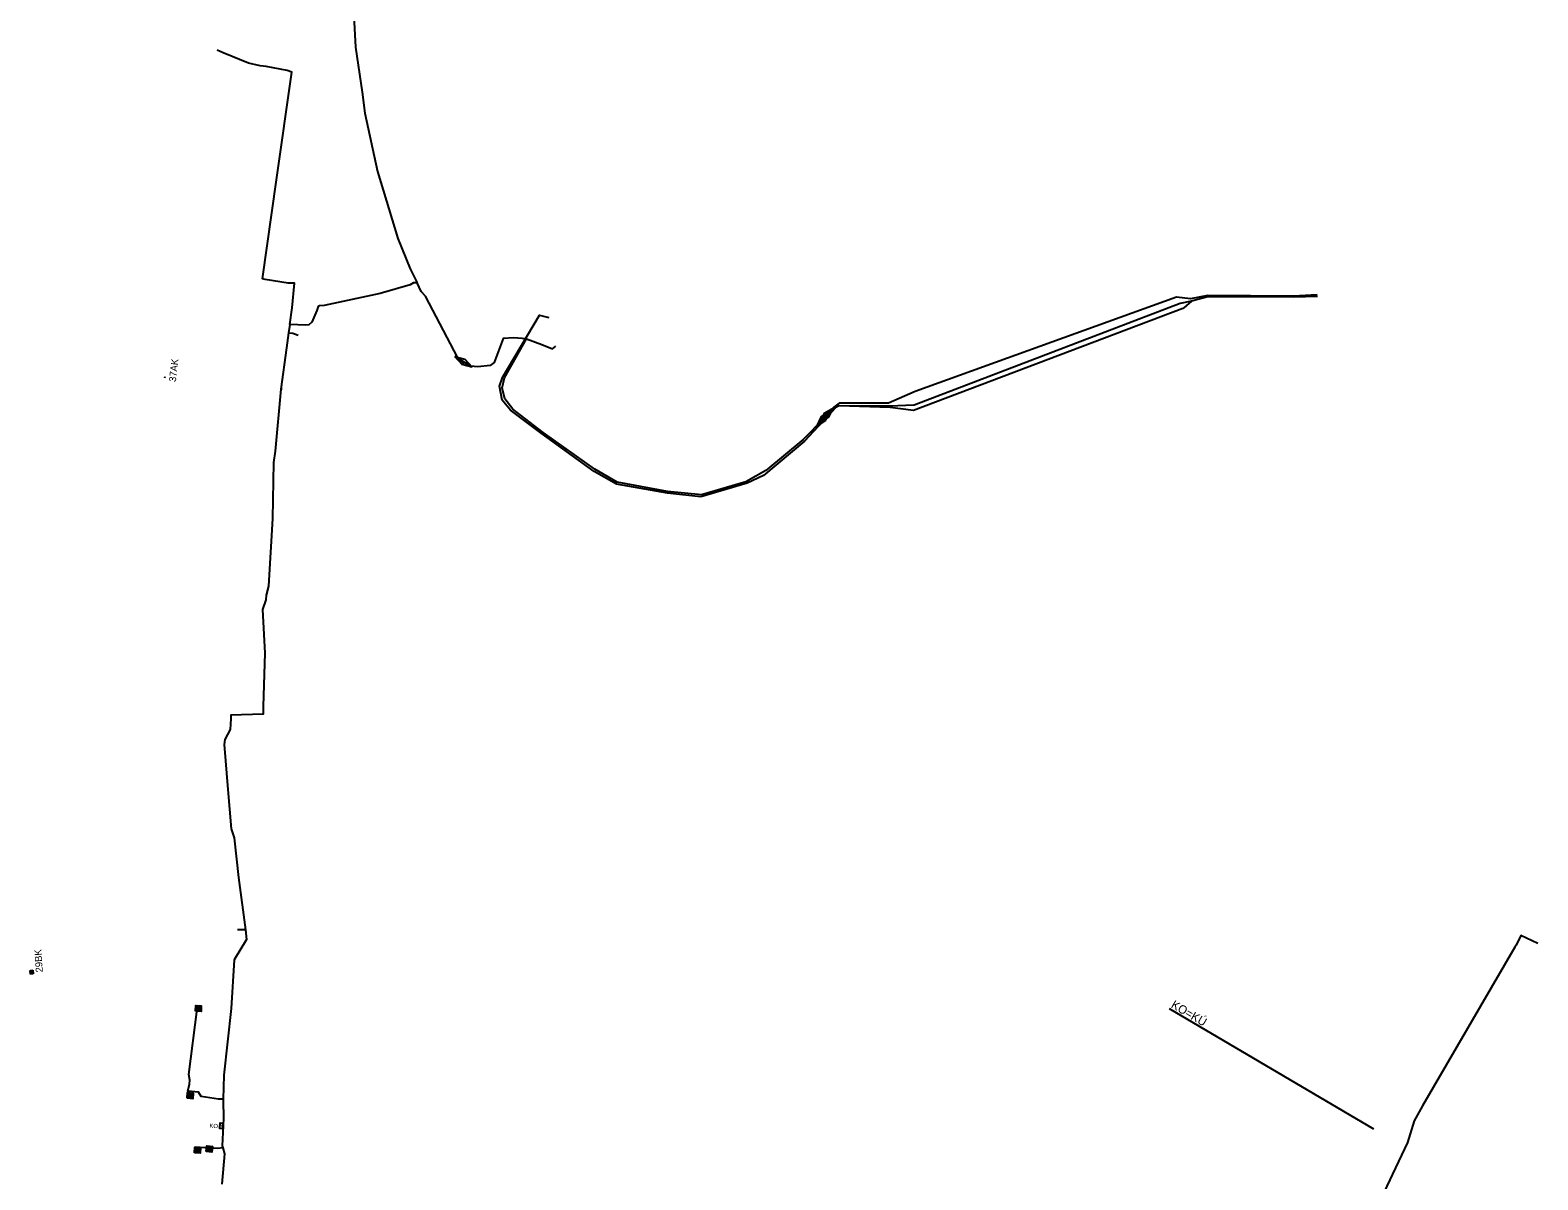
# Model space of a CAD drawing. Extents: x -598638 to -597933, y -1164002 to -1161904.
# Drawn here: x -598468 to -597933, y -1162612 to -1162205 of the extents above; entities that cross this region are included whole.
import ezdxf

# ---------------------------------------------------------------- set-up
doc = ezdxf.new("R2010")
doc.units = 0
for name, color, linetype in [('Vrstva 1', 7, 'Continuous'), ('Vrstva 11', 7, 'Continuous'), ('Vrstva 12', 7, 'Continuous'), ('Vrstva 25', 7, 'Continuous'), ('Vrstva 26', 7, 'Continuous'), ('Vrstva 28', 7, 'Continuous'), ('Vrstva 3', 7, 'Continuous'), ('Vrstva 31', 7, 'Continuous'), ('Vrstva 36', 7, 'Continuous')]:
    doc.layers.add(name, color=color, linetype=linetype)

msp = doc.modelspace()

# ---------------------------------------------------------------- linework, layer by layer
at = {"layer": 'Vrstva 1'}
msp.add_line((-598064.09, -1162551.17), (-597991.64, -1162593.75), dxfattribs=at)
at = {"layer": 'Vrstva 12'}
for p, q in [((-598467.77, -1162537.62), (-598466.85, -1162537.57)), ((-598467.68, -1162538.96), (-598467.77, -1162537.62)), ((-598466.73, -1162538.87), (-598467.68, -1162538.96)), ((-598466.85, -1162537.57), (-598466.73, -1162538.87))]:
    msp.add_line(p, q, dxfattribs=at)
at = {"layer": 'Vrstva 25'}
msp.add_lwpolyline([(-598399.55, -1162593.72), (-598400.55, -1162593.67), (-598400.45, -1162591.67), (-598399.45, -1162591.72), (-598399.55, -1162593.72)], dxfattribs=at)
at = {"layer": 'Vrstva 26'}
for points in [[(-598011.45, -1162298.92), (-598019.97, -1162299.17), (-598050.29, -1162298.98), (-598056.17, -1162300.49), (-598058.88, -1162302.93)], [(-598060.11, -1162301.37), (-598154.38, -1162337.34), (-598163.12, -1162337.7), (-598181.03, -1162337.65), (-598182.25, -1162338.25), (-598193.26, -1162350.18), (-598207.85, -1162362.29), (-598213.6, -1162365.05), (-598230, -1162369.89), (-598241.82, -1162368.56), (-598259.92, -1162365.37), (-598267.91, -1162360.87), (-598286.7, -1162347.32), (-598297.52, -1162339.13), (-598300.49, -1162335.57), (-598301.41, -1162330.6), (-598300.36, -1162327.61), (-598287.22, -1162305.48), (-598283.93, -1162306.33)], [(-598058.88, -1162302.93), (-598059.2, -1162303.1), (-598154.64, -1162339.27), (-598162.93, -1162338.26), (-598181.03, -1162337.65)], [(-598056.17, -1162300.49), (-598060.11, -1162301.37)]]:
    msp.add_lwpolyline(points, dxfattribs=at)
at = {"layer": 'Vrstva 28'}
msp.add_line((-598376.94, -1162317.06), (-598378.88, -1162331.68), dxfattribs=at)
for points in [[(-598353.9, -1162184.09), (-598352.41, -1162210.55), (-598350.05, -1162226.44), (-598349.11, -1162233.96), (-598344.67, -1162254.61), (-598337.45, -1162278.29), (-598333.08, -1162289.1), (-598330.61, -1162294.08)], [(-598375.78, -1162308.82), (-598374.85, -1162302.85), (-598374.07, -1162294.15), (-598376.34, -1162294.11), (-598384.44, -1162292.82), (-598385.42, -1162292.58), (-598380.46, -1162257.51), (-598375.06, -1162219.37), (-598376.64, -1162218.79), (-598384.12, -1162217.4), (-598386.19, -1162217.16), (-598390.41, -1162216.19), (-598399.4, -1162212.6), (-598401.45, -1162211.61)], [(-598330.61, -1162294.08), (-598331.9, -1162294.01), (-598333.02, -1162294.74), (-598343.76, -1162297.84), (-598363.52, -1162302.05), (-598365.21, -1162302.15), (-598365.71, -1162302.43), (-598366.21, -1162303.85), (-598367.94, -1162308.01), (-598369.04, -1162308.96), (-598370.03, -1162309.04), (-598375.78, -1162308.82), (-598376.18, -1162311.7), (-598376.94, -1162317.06)], [(-598376.18, -1162311.7), (-598374.7, -1162311.85), (-598372.76, -1162312.62)], [(-598378.5, -1162331.73), (-598378.88, -1162331.68), (-598380.93, -1162353.73), (-598381.48, -1162357.65), (-598381.89, -1162377.53), (-598383.31, -1162401.46), (-598384.09, -1162404.69), (-598384.23, -1162406.31), (-598385.47, -1162409.72), (-598384.6, -1162425.24), (-598385.17, -1162443.97), (-598385.21, -1162446.81), (-598396.64, -1162447.23), (-598396.63, -1162448.48), (-598396.85, -1162452.27), (-598398.8, -1162455.76), (-598398.99, -1162457.62), (-598397.75, -1162473.54), (-598396.55, -1162487.5), (-598395.42, -1162490.7), (-598393.97, -1162504.76), (-598391.49, -1162523.29), (-598391.04, -1162526.62), (-598395.41, -1162533.9), (-598396.52, -1162551.17), (-598399.1, -1162574.72), (-598399.38, -1162583.21), (-598399.4, -1162583.79), (-598399.26, -1162589.82), (-598399.4, -1162592.7), (-598399.72, -1162599.74), (-598399.5, -1162600.49), (-598398.9, -1162602.55), (-598399.81, -1162613.38)], [(-598391.49, -1162523.29), (-598394.32, -1162523.26)], [(-597933.37, -1162528.05), (-597939.36, -1162525.29), (-597941.1, -1162528.7), (-597941.55, -1162529.41), (-597974.27, -1162585.61), (-597977.15, -1162590.9), (-597979.51, -1162598.61), (-597991.15, -1162623.06), (-598003.68, -1162641.63), (-598026.57, -1162675.67), (-598042.6, -1162699.78), (-598060.46, -1162726.16), (-598080.92, -1162759.23), (-598091.38, -1162776.88), (-598100.13, -1162791.04)], [(-598399.38, -1162583.21), (-598401.01, -1162583.26), (-598407.18, -1162582.31), (-598408.06, -1162580.8), (-598411.86, -1162580.41), (-598411.34, -1162577.93), (-598411.15, -1162576.51), (-598411.49, -1162574.44), (-598408.61, -1162551.32), (-598409.15, -1162551.04)], [(-598411.86, -1162580.41), (-598412.03, -1162581.9)], [(-598399.4, -1162592.7), (-598400, -1162592.7)], [(-598399.5, -1162600.49), (-598401.2, -1162600.74), (-598404.88, -1162600.51), (-598405.9, -1162600.5), (-598409.05, -1162600.18), (-598409.47, -1162601.28)], [(-598404.88, -1162600.51), (-598405.24, -1162600.75)]]:
    msp.add_lwpolyline(points, dxfattribs=at)
at = {"layer": 'Vrstva 3'}
for p, q in [((-598407.74, -1162552.12), (-598409.12, -1162550.57)), ((-598407.21, -1162552.15), (-598409.09, -1162550.04)), ((-598407.18, -1162551.62), (-598408.56, -1162550.07)), ((-598407.15, -1162551.1), (-598408.04, -1162550.1)), ((-598407.12, -1162550.57), (-598407.51, -1162550.13)), ((-598408.8, -1162552.06), (-598409.19, -1162551.63)), ((-598408.27, -1162552.09), (-598409.16, -1162551.1)), ((-598411.71, -1162582.93), (-598412.08, -1162582.49)), ((-598411.18, -1162582.97), (-598412.04, -1162581.96)), ((-598410.65, -1162583.02), (-598412, -1162581.43)), ((-598410.12, -1162583.06), (-598411.95, -1162580.91)), ((-598410.08, -1162582.53), (-598411.43, -1162580.95)), ((-598410.03, -1162582), (-598410.9, -1162580.99)), ((-598409.99, -1162581.47), (-598410.37, -1162581.03)), ((-598409.14, -1162602.31), (-598409.51, -1162601.87)), ((-598408.61, -1162602.35), (-598409.48, -1162601.34)), ((-598408.08, -1162602.38), (-598409.44, -1162600.82)), ((-598407.55, -1162602.42), (-598409.4, -1162600.29)), ((-598407.51, -1162601.89), (-598408.87, -1162600.32)), ((-598407.47, -1162601.36), (-598408.35, -1162600.36)), ((-598407.44, -1162600.84), (-598407.82, -1162600.4)), ((-598404.93, -1162601.79), (-598405.3, -1162601.34)), ((-598404.4, -1162601.84), (-598405.24, -1162600.81)), ((-598403.87, -1162601.89), (-598405.19, -1162600.28)), ((-598403.35, -1162601.95), (-598405.14, -1162599.75)), ((-598403.29, -1162601.42), (-598404.61, -1162599.81)), ((-598403.24, -1162600.89), (-598404.08, -1162599.86)), ((-598403.19, -1162600.36), (-598403.55, -1162599.91))]:
    msp.add_line(p, q, dxfattribs=at)
for points in [[(-598409.21, -1162552.04), (-598409.09, -1162550.04), (-598407.1, -1162550.16), (-598407.21, -1162552.15)], [(-598409.21, -1162552.04), (-598409.09, -1162550.04), (-598407.1, -1162550.16), (-598407.21, -1162552.15)], [(-598412.11, -1162582.9), (-598411.95, -1162580.91), (-598409.96, -1162581.06), (-598410.12, -1162583.06)], [(-598412.11, -1162582.9), (-598411.95, -1162580.91), (-598409.96, -1162581.06), (-598410.12, -1162583.06)], [(-598409.54, -1162602.28), (-598409.4, -1162600.29), (-598407.41, -1162600.43), (-598407.55, -1162602.42)], [(-598409.54, -1162602.28), (-598409.4, -1162600.29), (-598407.41, -1162600.43), (-598407.55, -1162602.42)], [(-598405.34, -1162601.74), (-598405.14, -1162599.75), (-598403.15, -1162599.96), (-598403.35, -1162601.95)], [(-598405.34, -1162601.74), (-598405.14, -1162599.75), (-598403.15, -1162599.96), (-598403.35, -1162601.95)]]:
    msp.add_lwpolyline(points, close=True, dxfattribs=at)
for points in [[(-598409.21, -1162552.04), (-598409.09, -1162550.04), (-598407.1, -1162550.16), (-598407.21, -1162552.15), (-598409.21, -1162552.04)], [(-598409.21, -1162552.04), (-598409.09, -1162550.04), (-598407.1, -1162550.16), (-598407.21, -1162552.15), (-598409.21, -1162552.04)], [(-598412.11, -1162582.9), (-598411.95, -1162580.91), (-598409.96, -1162581.06), (-598410.12, -1162583.06), (-598412.11, -1162582.9)], [(-598412.11, -1162582.9), (-598411.95, -1162580.91), (-598409.96, -1162581.06), (-598410.12, -1162583.06), (-598412.11, -1162582.9)], [(-598409.54, -1162602.28), (-598409.4, -1162600.29), (-598407.41, -1162600.43), (-598407.55, -1162602.42), (-598409.54, -1162602.28)], [(-598409.54, -1162602.28), (-598409.4, -1162600.29), (-598407.41, -1162600.43), (-598407.55, -1162602.42), (-598409.54, -1162602.28)], [(-598405.34, -1162601.74), (-598405.14, -1162599.75), (-598403.15, -1162599.96), (-598403.35, -1162601.95), (-598405.34, -1162601.74)], [(-598405.34, -1162601.74), (-598405.14, -1162599.75), (-598403.15, -1162599.96), (-598403.35, -1162601.95), (-598405.34, -1162601.74)]]:
    msp.add_lwpolyline(points, dxfattribs=at)
at = {"layer": 'Vrstva 31'}
for p, q in [((-598374.69, -1162302.88), (-598374.85, -1162302.85)), ((-598376.94, -1162317.06), (-598378.88, -1162331.68)), ((-598317.08, -1162320.35), (-598316.95, -1162320.35)), ((-598316.53, -1162320.99), (-598316.08, -1162320.88)), ((-598315.63, -1162321.96), (-598314.69, -1162321.73)), ((-598315.03, -1162322.58), (-598313.78, -1162322.28)), ((-598313.14, -1162323.31), (-598312.39, -1162323.13)), ((-598311.67, -1162323.7), (-598311.52, -1162323.66)), ((-598378.5, -1162331.73), (-598378.88, -1162331.68)), ((-598186.84, -1162342.83), (-598186.86, -1162342.37)), ((-598186.72, -1162343.41), (-598186.79, -1162342.43)), ((-598186.01, -1162342.92), (-598186.1, -1162341.64)), ((-598185.71, -1162342.16), (-598185.73, -1162341.18)), ((-598184.98, -1162341.17), (-598185.04, -1162340.4)), ((-598184.97, -1162341.7), (-598185.01, -1162340.42)), ((-598184.36, -1162339.78), (-598184.37, -1162339.63)), ((-598183.86, -1162340), (-598183.88, -1162339.23)), ((-598183.18, -1162338.65), (-598183.18, -1162338.49)), ((-598188.54, -1162344.57), (-598188.53, -1162344.44)), ((-598187.83, -1162344.13), (-598187.86, -1162343.67)), ((-598187.58, -1162343.24), (-598187.56, -1162343.11))]:
    msp.add_line(p, q, dxfattribs=at)
for points in [[(-598327.69, -1162298.73), (-598329.22, -1162297.16), (-598330.61, -1162294.08), (-598331.9, -1162294.01), (-598333.02, -1162294.74), (-598343.76, -1162297.84), (-598363.52, -1162302.05), (-598365.21, -1162302.15), (-598365.71, -1162302.43), (-598366.21, -1162303.85), (-598367.94, -1162308.01), (-598369.04, -1162308.96), (-598370.03, -1162309.04), (-598375.78, -1162308.82), (-598376.18, -1162311.7), (-598376.94, -1162317.06)], [(-598061.46, -1162299.14), (-598154.03, -1162332.56), (-598163.58, -1162336.7), (-598180.97, -1162336.66), (-598182.85, -1162338.14), (-598185.41, -1162340.84), (-598186.48, -1162342.08), (-598193.72, -1162349.57), (-598207.03, -1162360.58), (-598214.06, -1162364.58), (-598229.83, -1162369.12), (-598241.88, -1162367.95), (-598259.75, -1162364.67), (-598267.63, -1162360.05), (-598285.94, -1162347.05), (-598296.65, -1162338.75), (-598299.49, -1162335.12), (-598300.47, -1162331.19), (-598299.61, -1162327.73), (-598291.89, -1162313.9), (-598296.42, -1162313.54), (-598300.11, -1162313.75), (-598303.32, -1162322.26), (-598304.74, -1162323.34), (-598309.11, -1162323.77), (-598311.69, -1162323.56), (-598314.28, -1162321.98), (-598316.12, -1162320.55), (-598327.69, -1162298.73)], [(-598011.58, -1162298.27), (-598019.98, -1162298.75), (-598050.31, -1162298.5), (-598056.43, -1162299.75), (-598061.46, -1162299.14)], [(-598375.78, -1162308.82), (-598374.85, -1162302.85)], [(-598291.89, -1162313.9), (-598286.45, -1162315.92), (-598282.62, -1162317.37), (-598281.48, -1162316.42)], [(-598317.29, -1162320.14), (-598313.75, -1162321.11), (-598311.27, -1162323.81)], [(-598378.5, -1162331.73), (-598378.88, -1162331.68), (-598380.93, -1162353.73), (-598381.48, -1162357.65), (-598381.89, -1162377.53), (-598383.31, -1162401.46), (-598384.09, -1162404.69), (-598384.23, -1162406.31), (-598385.47, -1162409.72), (-598384.6, -1162425.24), (-598385.17, -1162443.97), (-598385.21, -1162446.81), (-598396.64, -1162447.23), (-598396.63, -1162448.48), (-598396.85, -1162452.27), (-598398.8, -1162455.76), (-598398.99, -1162457.62), (-598397.75, -1162473.54), (-598396.55, -1162487.5), (-598395.42, -1162490.7), (-598393.97, -1162504.76), (-598391.49, -1162523.29), (-598391.04, -1162526.62), (-598395.41, -1162533.9), (-598396.52, -1162551.17), (-598399.1, -1162574.72), (-598399.38, -1162583.21), (-598399.4, -1162583.79), (-598399.26, -1162589.82), (-598399.4, -1162592.7), (-598399.72, -1162599.74), (-598399.5, -1162600.49), (-598398.9, -1162602.55), (-598399.81, -1162613.38)], [(-598188.79, -1162344.74), (-598187.26, -1162341.41), (-598184.18, -1162339.41)], [(-598187.83, -1162343.4), (-598186.15, -1162340.14), (-598182.98, -1162338.28)]]:
    msp.add_lwpolyline(points, dxfattribs=at)
for points in [[(-598317.29, -1162320.14), (-598314.81, -1162322.84), (-598311.27, -1162323.81)], [(-598188.79, -1162344.74), (-598185.71, -1162342.74), (-598184.18, -1162339.41)], [(-598187.83, -1162343.4), (-598184.67, -1162341.54), (-598182.98, -1162338.28)]]:
    msp.add_lwpolyline(points, close=True, dxfattribs=at)
at = {"layer": 'Vrstva 36'}
for p, q in [((-598419.98, -1162327.71), (-598419.9, -1162327.22)), ((-598467.31, -1162537.99), (-598467.27, -1162538.49))]:
    msp.add_line(p, q, dxfattribs=at)

# ---------------------------------------------------------------- texts
at = {"layer": 'Vrstva 1'}
msp.add_text('KO=KÚ', height=3, rotation=329.556, dxfattribs=at).set_placement((-598063.65, -1162550.61))
at = {"layer": 'Vrstva 11'}
for s, rotation, p in [('37AK', 83.2508, (-598416.14, -1162329.24)), ('29BK', 93.7932, (-598463.26, -1162538.24))]:
    msp.add_text(s, height=2.5, rotation=rotation, dxfattribs=at).set_placement(p)
at = {"layer": 'Vrstva 25'}
msp.add_text('KO1', height=1.5, rotation=357.235, dxfattribs=at).set_placement((-598404.23, -1162593.38))

doc.saveas('drawing.dxf')
